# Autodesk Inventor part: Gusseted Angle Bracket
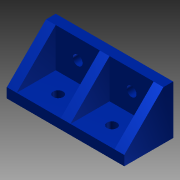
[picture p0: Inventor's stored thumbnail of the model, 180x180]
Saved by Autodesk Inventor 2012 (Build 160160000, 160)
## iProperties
Created: 2014-02
Part Number: Gusseted Angle Bracket
Material: Default
Document SubType Name: Modeling
Designer: Aser
Density: 1 g/cm^3
Author: Aser
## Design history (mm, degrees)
sketch "Sketch1"
  geometry: L1 (0, 0)-(0, 30); L2 (0, 30)-(30, 30); L3 (30, 30)-(30, 24); L4 (30, 24)-(6, 24); L5 (6, 24)-(6, 0); L6 (6, 0)-(0, 0)
  constraints: 12 end point, 4 parallel, 1 perpendicular, 1 vertical
  dimensions: "d0" = 30 distance of L1.start L1.end; "d1" = 30 distance of L1.end L2.end; "d2" = 6 distance of L2.end L3.end; "d3" = 24 distance of L3.end L4.end
extrude "Extrusion1" new body sketch "Sketch1" distance "d4" = 60; taper "d5" = 0 deg
sketch "Sketch2"
  geometry: L1 (-30, 0)-(-30, 30) reference; L2 (0, 0)-(-30, 0) reference; L3 (0, 6)-(0, 0) reference; L4 (-24, 6)-(0, 6) reference; L5 (-24, 30)-(-24, 6) reference; L6 (-30, 30)-(-24, 30) reference; L7 (-24, 30)-(0, 6)
  constraints: 2 end point
extrude "Extrusion2" join sketch "Sketch2" distance "d6" = 6; taper "d7" = 0 deg
sketch "Sketch3"
  geometry: L1 (0, 0)-(30, 0) reference; L2 (30, 0)-(30, 30) reference; L3 (30, 30)-(24, 30) reference; L4 (24, 30)-(24, 6) reference; L5 (24, 6)-(0, 6) reference; L6 (0, 6)-(0, 0) reference; L7 (24, 30)-(24, 6) reference; L8 (0, 6)-(24, 30) reference; L9 (24, 6)-(0, 6) reference
extrude "Extrusion3" join sketch "Sketch3" distance "d8" = 6; taper "d9" = 0 deg
sketch "Sketch5"
  geometry: L1 (60, 0)-(0, 0) reference; L2 (60, 24)-(0, 24) reference; L3 (30, 24)-(30, 0); L4 (30, 24)-(27, 24); L5 (27, 24)-(27, 0); L6 (27, 0)-(30, 0); L7 (30, 0)-(30, 24); L8 (30, 24)-(33, 24); L9 (33, 24)-(33, 0); L10 (33, 0)-(30, 0); L11 (30, 0)-(30, 24); 1 further point
  constraints: 18 end point, 4 parallel, 2 horizontal, 2 midpoint, 2 perpendicular, 2 point on line
  dimensions: "d19" = 3 distance of L6.end L5.end; "d20" = 3 distance of L9.end L10.end
extrude "Extrusion5" join sketch "Sketch5" distance "d21" = 24; taper "d22" = 0 deg
sketch "Sketch6"
  geometry: L1 (-24, 24)-(-24, 0) reference; L2 (0, 24)-(0, 0) reference; L3 (-24, -6)-(-24, 0) reference; L4 (6, -6)-(-24, -6) reference; L5 (6, 24)-(6, -6) reference; L6 (0, 24)-(6, 24) reference; L7 (-24, 0)-(0, 24) reference; L8 (-24, 24)-(0, 24); L9 (0, 24)-(-24, 0); L10 (-24, 0)-(-24, 24); 1 further point
  constraints: 6 end point, 2 collinear, 1 perpendicular
extrude "Extrusion6" cut sketch "Sketch6" distance "d23" = 24; taper "d24" = 0 deg
sketch "Sketch7"
  geometry: L1 (27, 0)-(27, 24) reference; L2 (27, 24)-(0, 24) reference; L3 (33, 24)-(33, 0) reference; L4 (60, 0)-(33, 0) reference; L5 (60, 24)-(60, 0) reference; L6 (60, 24)-(33, 24) reference; C1 r 3 at (13.5, 12); C2 r 3 at (46.5, 12); 2 further points
  constraints: 2 centre point
  dimensions: "d28" = 6 diameter of C1; "d29" = 27 distance of L1.end L2.end (derived); "d30" = 24 distance of L2.end point (0, 0) (derived); "d31" = 12 distance from line of L2 C1.centre; "d32" = 13.5 distance from line of L1 C1.centre; "d33" = 6 diameter of C2; "d34" = 12 distance from line of L6 C2.centre; "d35" = 13.5 distance from line of C2.centre L3
extrude "Extrusion7" cut sketch "Sketch7" distance "d36" = 10; taper "d37" = 0 deg
sketch "Sketch8"
  geometry: L1 (-27, 24)-(-27, 0) reference; L2 (-27, 24)-(0, 24) reference; L3 (-33, 0)-(-33, 24) reference; L4 (-60, 24)-(-33, 24) reference; L5 (-60, 0)-(-60, 24) reference; L6 (-60, 0)-(-33, 0) reference; C1 r 3 at (-46.5, 12); C2 r 3 at (-13.5, 12); 1 further point
  constraints: 2 centre point
  dimensions: "d38" = 6 diameter of C1; "d39" = 6 diameter of C2; "d40" = 12 distance from line of L4 C1.centre; "d41" = 13.5 distance from line of C1.centre L5; "d42" = 12 distance from line of L2 C2.centre; "d43" = 13.5 distance from line of C2.centre L1
extrude "Extrusion8" cut sketch "Sketch8" distance "d44" = 10; taper "d45" = 0 deg
body "Solid1"
node "Projected Loop1"
node "Projected Loop2"
node "Projected Loop3"
node "Projected Loop4"
